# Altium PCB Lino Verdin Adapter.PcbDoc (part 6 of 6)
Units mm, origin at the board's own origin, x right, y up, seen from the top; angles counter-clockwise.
Board outline 69.6 x 35 mm, 8 copper layers (Top Layer, Mid 1, GND 1, Mid 2, Mid 3, GND 2, Mid 4, Bottom Layer), stack 1.198 mm thick; 208 components, 258 nets, 1063 pads, 1090 vias.
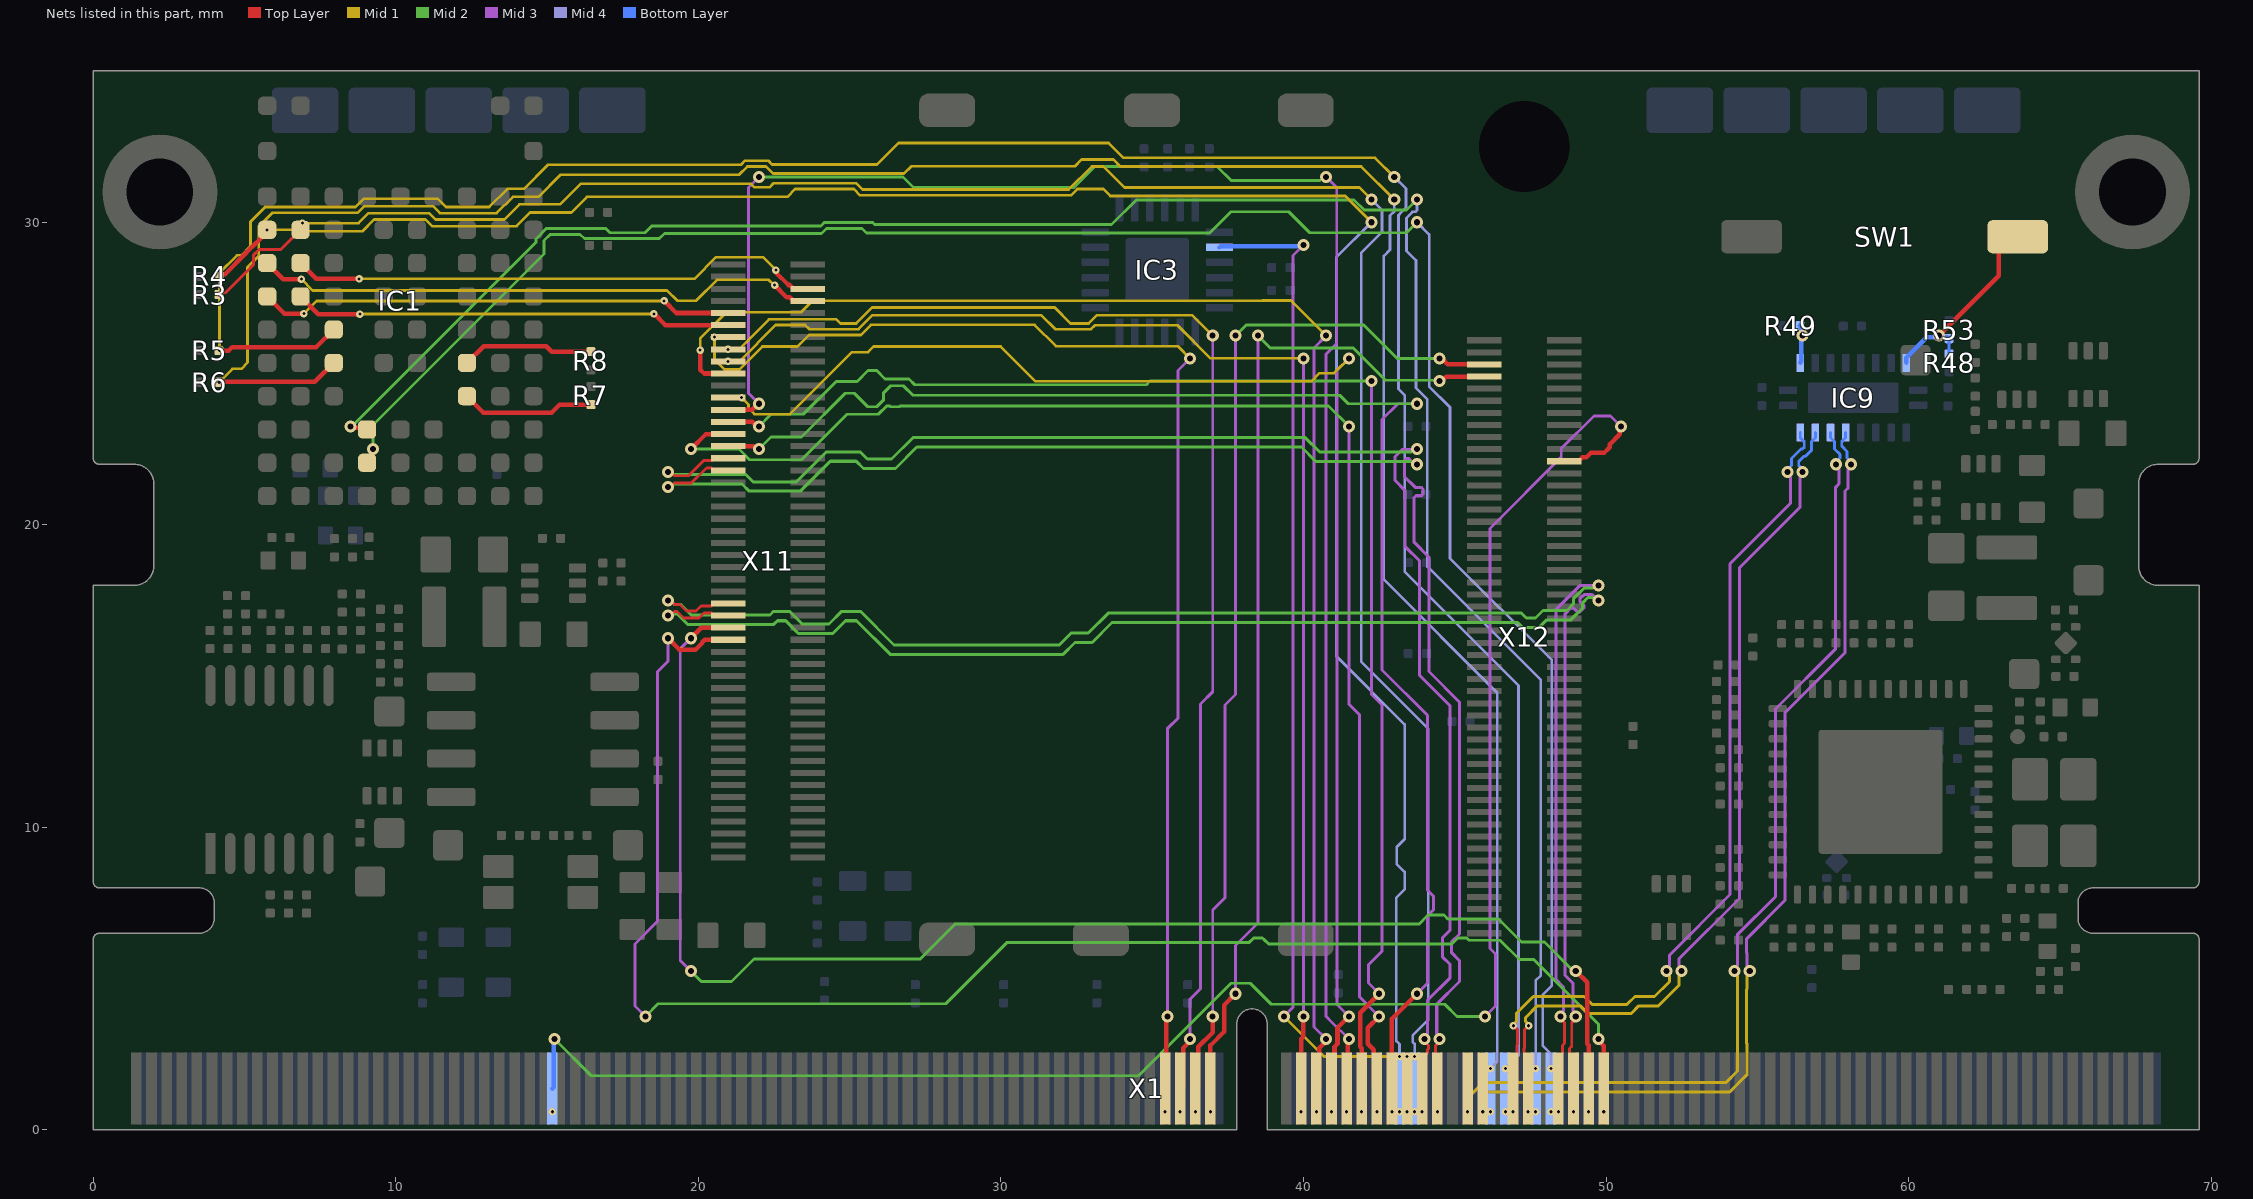
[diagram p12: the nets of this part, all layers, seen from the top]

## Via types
v1: diameter 0.4, hole 0.2, Top Layer to Bottom Layer, tented both sides, 600 vias
v2: diameter 0.25, hole 0.1, Mid 4 to Bottom Layer, tented both sides, 229 vias
v3: diameter 0.25, hole 0.1, Top Layer to Mid 1, tented both sides, 216 vias
v4: diameter 0.25, hole 0.1, Top Layer to Mid 1, tented top, 41 vias
v5: diameter 0.4, hole 0.2, Top Layer to Bottom Layer, 4 vias

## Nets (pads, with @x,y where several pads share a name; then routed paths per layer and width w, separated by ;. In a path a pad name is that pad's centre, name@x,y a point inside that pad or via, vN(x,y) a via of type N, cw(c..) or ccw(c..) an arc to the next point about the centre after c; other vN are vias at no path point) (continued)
SPI_2_MOSI: X1.56 X12.S22 | length 59.7
  Top Layer w0.15: X12.S22@48.62,22.1 48.645,22.125 49.115,22.125 49.215,22.225 49.341,22.225 49.491,22.375 49.935,22.375 50.125,22.565 50.125,22.655 50.459,22.99 50.459,23.209 v1(50.5,23.25)
  Mid 3 w0.095: v1(46,3.75) 46.35,4.1 46.35,5.81 46.16,6 46.16,19.88 48.522,22.242 48.522,22.522 49.598,23.598 50.152,23.598 v1(50.5,23.25)
  Mid 2 w0.095: v1(15.25,3) 16.46,1.79 34.549,1.79 36.106,3.347 37.606,4.848 38.243,4.848 38.938,4.152 44.668,4.152 45.07,3.75 v1(46,3.75)
  Bottom Layer w0.15: X1.56@15.175,1.362 15.213,1.4 15.213,2.963 v1(15.25,3)
  other v2: 15.175,0.6
UART_1_CTS: IC1.H8 X11.P6 | length 17.8
  Top Layer w0.15: IC1.H8@6.85,28.65 7.37,28.13 v3(8.79,28.13) ; v3(22.56,28.42) 22.579,28.401 22.579,28.323 22.978,27.925 23.025,27.925 23.125,27.825 23.595,27.825 X11.P6@23.62,27.8
  Mid 1 w0.09: v3(8.79,28.13) 19.868,28.13 20.583,28.845 22.143,28.845 22.56,28.428 v3(22.56,28.42)
UART_1_RTS: IC1.H9 X11.P8 | length 19
  Top Layer w0.15: IC1.H9@5.75,28.65 6.28,28.12 v3(6.88,28.12) ; v3(22.52,27.92) 22.915,27.525 23.025,27.525 23.125,27.425 23.595,27.425 X11.P8@23.62,27.4
  Mid 1 w0.09: v3(6.88,28.12) 7.253,27.747 18.965,27.747 19.307,27.405 19.925,27.405 20.615,28.095 22.327,28.095 22.502,27.92 v3(22.52,27.92)
UART_1_RXD: IC1.G8 X11.P11 | length 14.5
  Top Layer w0.15: IC1.G8@6.85,27.55 7.44,26.96 v3(8.81,26.96) ; v4(18.53,26.97) 18.543,26.97 18.913,26.6 X11.P11@20.98,26.6
  Mid 1 w0.09: v3(8.81,26.96) 8.815,26.965 18.525,26.965 v4(18.53,26.97)
UART_1_TXD: IC1.G9 X11.P9 | length 15.8
  Top Layer w0.15: IC1.G9@5.75,27.55 6.32,26.98 v3(6.96,26.98) ; v4(18.87,27.4) 19.27,27 X11.P9@20.98,27
  Mid 1 w0.09: v3(6.96,26.98) 7.38,27.4 v4(18.87,27.4)
UART_2_CTS: X1.143 X12.S7 | length 33.7
  Top Layer w0.15: X1.143@36.925,1.362 36.925,2.791 37.375,3.241 37.375,4.125 v1(37.75,4.5) ; v1(44.5,24.75) 44.568,24.75 44.718,24.9 X12.S7@45.98,24.9
  Mid 3 w0.095: v1(37.75,4.5) 37.75,6.09 38.5,6.84 v1(38.5,26.25)
  Mid 2 w0.095: v1(38.5,26.25) 38.902,25.847 41.644,25.847 42.716,24.776 44.474,24.776 v1(44.5,24.75)
  other v3: 36.925,0.6
UART_2_RTS: X1.141 X12.S5 | length 34.3
  Top Layer w0.15: X1.141@36.425,1.362 36.525,1.462 36.525,2.745 37,3.22 v1(37,3.75) ; v1(44.5,25.5) 44.568,25.5 44.768,25.3 X12.S5@45.98,25.3
  Mid 3 w0.095: v1(37,3.75) 37,7.27 37.403,7.673 37.403,13.356 37.403,14.042 37.75,14.39 v1(37.75,26.25)
  Mid 2 w0.095: v1(37.75,26.25) 38.097,26.597 42.003,26.597 43.1,25.5 v1(44.5,25.5)
  other v3: 36.425,0.6
UART_2_RXD: X1.137 X11.P13 | length 42.1
  Top Layer w0.15: X1.137@35.425,1.362 35.463,1.4 35.463,3.712 v1(35.5,3.75)
  Mid 3 w0.095: v1(35.5,3.75) 35.5,13.259 35.848,13.606 35.848,25.097 v1(36.25,25.5)
  Mid 1 w0.09: v4(20.53,26.2) 20.53,25.468 20.868,25.13 21.355,25.13 22.115,25.89 23.27,25.89 23.655,26.275 25.372,26.275 25.707,26.61 31.11,26.61 31.815,25.905 35.845,25.905 v1(36.25,25.5)
  other v3: 35.425,0.6
UART_2_TXD: X1.139 X11.P15 | length 42.6
  Top Layer w0.15: X1.139@35.925,1.362 36.025,1.462 36.025,2.707 36.25,2.932 v1(36.25,3)
  Mid 3 w0.095: v1(36.25,3) 36.25,4.32 36.598,4.668 36.598,14.08 37,14.483 v1(37,26.25)
  Mid 1 w0.09: v4(20.98,25.8) 21.34,25.8 22.33,26.79 24.56,26.79 24.695,26.655 25.214,26.655 25.739,27.18 31.78,27.18 32.305,26.655 32.898,26.655 33.173,26.93 36.32,26.93 v1(37,26.25)
  other v3: 35.925,0.6
UART_3_RXD: X1.147 X11.P17 | length 44.6
  Top Layer w0.15: X1.147@39.925,1.362 39.925,3.005 40,3.08 v1(40,3.75)
  Mid 3 w0.095: v1(40,3.75) v1(40,25.5)
  Mid 1 w0.09: v4(20.98,25.4) 21.356,25.4 22.556,26.6 23.53,26.6 23.665,26.465 25.293,26.465 25.758,26.93 31.33,26.93 31.795,26.465 32.977,26.465 33.107,26.595 35.836,26.595 36.931,25.5 v1(40,25.5)
  other v3: 39.925,0.6
UART_3_TXD: X1.149 X11.P19 | length 49
  Top Layer w0.15: v3(20.06,25.77) 20.06,25.128 20.188,25 X11.P19@20.98,25 ; X1.149@40.425,1.362 40.525,1.462 40.525,2.707 40.75,2.932 v1(40.75,3)
  Mid 3 w0.095: v1(40.75,3) 40.348,3.402 40.348,25.848 v1(40.75,26.25)
  Mid 1 w0.09: v3(20.06,25.77) 20.06,26.16 20.925,27.025 23.395,27.025 23.775,27.405 31.607,27.405 38.643,27.405 38.648,27.41 39.59,27.41 v1(40.75,26.25)
  other v3: 40.425,0.6
UART_4_RXD: X1.151 X11.P23 | length 47.2
  Top Layer w0.15: X11.P23@20.98,24.2 v4(21.43,24.2) ; X1.151@40.925,1.362 41.025,1.462 41.025,2.745 41.125,2.845 41.125,3.155 41.125,3.375 v1(41.5,3.75)
  Mid 3 w0.095: v1(41.5,3.75) 41.11,4.14 41.11,25.11 v1(41.5,25.5)
  Mid 1 w0.09: v4(21.43,24.2) 21.655,23.975 21.655,23.857 21.857,23.655 23.025,23.655 25.075,25.705 25.608,25.705 25.793,25.89 29.99,25.89 31.14,24.74 40.265,24.74 40.535,25.01 41.01,25.01 v1(41.5,25.5)
  other v3: 40.925,0.6
UART_4_TXD: X1.153 X11.P25 | length 59.1
  Top Layer w0.15: X11.P25@20.98,23.8 21.775,23.8 21.975,24 v1(22,24) ; X1.153@41.425,1.362 41.462,1.4 41.462,2.962 v1(41.5,3)
  Mid 3 w0.095: v1(22,24) 21.653,24.348 21.653,31.153 v1(22,31.5) ; v1(40.75,31.5) 41.1,31.15 41.1,25.99 40.75,25.64 40.75,3.75 40.945,3.555 v1(41.5,3)
  Mid 2 w0.095: v1(22,31.5) 26.759,31.5 27.106,31.153 32.411,31.153 33.106,31.848 37.144,31.848 37.611,31.38 40.547,31.38 40.667,31.5 v1(40.75,31.5)
  other v3: 41.425,0.6
USB_1_D_N: X1.163 X11.P33 | length 51.4
  Top Layer w0.095: v1(19,21.75) 19.077,21.75 19.208,21.619 19.669,21.619 20.169,22.119 20.429,22.119 20.51,22.2 X11.P33@20.98,22.2 ; X1.163@43.925,1.362 43.925,2.375 44.102,2.552 44.102,2.649 44.131,2.678 44.131,2.792 44,2.923 v1(44,3)
  Mid 3 w0.1: v1(43.75,22.5) 43.746,22.496 43.272,22.496 43.031,22.256 43.031,21.464 43.35,21.145 43.35,19.29 43.84,18.8 43.84,15.02 44.85,14.01 44.85,6.605 44.59,6.345 44.59,5.727 44.85,5.467 44.85,5.033 44.095,4.278 44.095,3.176 44,3.081 v1(44,3)
  Mid 2 w0.1: v1(19,21.75) 19.081,21.75 19.176,21.655 21.573,21.655 21.806,21.422 23.244,21.422 24.232,22.41 25.345,22.41 25.583,22.172 26.386,22.172 27.094,22.88 40.06,22.88 40.535,22.405 43.574,22.405 43.669,22.5 v1(43.75,22.5)
  other v3: 43.925,0.6
USB_1_D_P: X1.165 X11.P35 | length 51.3
  Top Layer w0.095: v1(19,21.25) 19.077,21.25 19.208,21.381 19.767,21.381 20.267,21.881 20.429,21.881 20.51,21.8 X11.P35@20.98,21.8 ; X1.165@44.425,1.362 44.369,1.418 44.369,2.792 44.5,2.923 v1(44.5,3)
  Mid 3 w0.1: v1(43.75,22) 43.669,22 43.483,22.186 43.4,22.186 43.341,22.127 43.341,21.592 43.693,21.24 43.891,21.24 43.95,21.181 43.95,21.019 43.891,20.96 43.719,20.96 43.66,20.901 43.66,19.418 44.15,18.928 44.15,15.148 45.16,14.138 45.16,6.477 44.9,6.217 44.9,5.855 45.16,5.595 45.16,4.905 44.405,4.15 44.405,3.176 44.5,3.081 v1(44.5,3)
  Mid 2 w0.1: v1(19,21.25) 19.081,21.25 19.176,21.345 21.445,21.345 21.678,21.112 23.372,21.112 24.36,22.1 25.217,22.1 25.455,21.862 26.514,21.862 27.222,22.57 39.932,22.57 40.407,22.095 43.574,22.095 43.669,22 v1(43.75,22)
  other v3: 44.425,0.6
USB_1_EN: X1.155 X11.P27 | length 46.5
  Top Layer w0.15: X11.P27@20.98,23.4 21.782,23.4 21.932,23.25 v1(22,23.25) ; X1.155@41.925,1.362 41.925,2.691 41.875,2.741 41.875,3.875 v1(42.5,4.5)
  Mid 3 w0.095: v1(42.25,24.75) 42.25,14.39 42.593,14.047 42.593,13.649 42.598,13.644 42.598,11.856 42.593,11.851 42.593,5.903 42.148,5.458 42.148,4.852 v1(42.5,4.5)
  Mid 2 w0.095: v1(22,23.25) 22.403,23.653 23.467,23.653 24.554,24.74 25.249,24.74 25.606,25.098 25.894,25.098 26.171,24.82 26.96,24.82 27.15,24.63 34.81,24.63 34.93,24.75 v1(42.25,24.75)
  other v3: 41.925,0.6
USB_1_ID: IC3.2 X1.161 | length 33.2
  Mid 3 w0.095: v1(39.35,3.75) 39.652,4.052 39.652,28.902 v1(40,29.25)
  Mid 1 w0.09: v1(39.35,3.75) 40.675,2.425 v3(43.425,2.425)
  Bottom Layer w0.15: IC3.2@37.22,29.172 37.259,29.211 39.961,29.211 v1(40,29.25)
  other v3: 43.425,0.6
USB_1_OC#: X1.157 X11.P29 | length 47
  Top Layer w0.15: v1(19.75,22.5) 20.25,23 X11.P29@20.98,23 ; X1.157@42.425,1.362 42.325,1.462 42.325,2.645 42.125,2.845 42.125,3.375 v1(42.5,3.75)
  Mid 3 w0.095: v1(41.5,23.255) 41.5,14.07 41.848,13.723 41.848,6.794 41.84,6.787 41.848,6.779 41.848,4.402 v1(42.5,3.75)
  Mid 2 w0.095: v1(19.75,22.5) 21.34,22.5 21.69,22.15 23.409,22.15 24.911,23.653 25.947,23.653 26.224,23.93 26.329,23.93 26.356,23.902 26.644,23.902 26.671,23.93 40.825,23.93 v1(41.5,23.255)
  other v3: 42.425,0.6
USB_1_VBUS: X1.159 X11.P31 | length 49.2
  Top Layer w0.15: X11.P31@20.98,22.6 21.832,22.6 21.932,22.5 v1(22,22.5) ; X1.159@42.925,1.362 42.925,3.675 v1(43.75,4.5)
  Mid 3 w0.095: v1(43.75,4.5) 44.098,4.847 44.098,7.08 44.293,7.275 44.293,7.725 44.098,7.92 44.098,13.702 42.6,15.2 42.6,23.48 43.12,24 v1(43.75,24)
  Mid 2 w0.095: v1(22,22.5) 22.403,22.903 23.411,22.903 24.856,24.348 25.153,24.348 25.597,23.903 25.894,23.903 26.125,24.134 26.125,24.366 26.356,24.597 26.773,24.597 27.09,24.28 41.2,24.28 41.48,24 v1(43.75,24)
  other v3: 42.925,0.6
USB_2_D_N: X1.181 X11.P57 | length 52.9
  Top Layer w0.095: v1(19,17.5) 19.077,17.5 19.208,17.369 19.39,17.369 19.606,17.153 19.92,17.153 20.086,17.319 20.429,17.319 20.51,17.4 X11.P57@20.98,17.4 ; X1.181@48.425,1.362 48.553,1.49 48.553,2.555 48.556,2.558 48.556,2.791 48.631,2.866 48.631,3.542 48.5,3.673 v1(48.5,3.75)
  Mid 3 w0.1: v1(48.5,3.75) 48.5,3.831 48.595,3.926 48.595,4.722 48.34,4.977 48.34,17.19 49.15,18 v1(49.75,18)
  Mid 2 w0.1: v1(19,17.5) 19.081,17.5 19.215,17.366 19.42,17.366 19.766,17.02 22.368,17.02 22.486,17.138 23.014,17.138 23.432,16.72 24.318,16.72 24.736,17.138 25.358,17.138 26.466,16.03 31.93,16.03 32.322,16.422 32.886,16.422 33.544,17.08 47.206,17.08 47.364,16.922 47.667,16.922 47.915,17.17 48.708,17.17 48.918,17.38 48.918,17.551 49.272,17.905 49.574,17.905 49.669,18 v1(49.75,18)
  other v3: 48.425,0.6
USB_2_D_P: X1.183 X11.P59 | length 52.9
  Top Layer w0.095: v1(19,17) 19.077,17 19.208,17.131 19.291,17.131 19.507,16.915 20.018,16.915 20.185,17.081 20.429,17.081 20.51,17 X11.P59@20.98,17 ; X1.183@48.925,1.362 48.797,1.49 48.797,2.555 48.794,2.558 48.794,2.693 48.869,2.768 48.869,3.542 49,3.673 v1(49,3.75)
  Mid 3 w0.1: v1(49,3.75) 49,3.831 48.905,3.926 48.905,4.85 48.65,5.105 48.65,17.062 48.838,17.249 48.921,17.249 49.049,17.121 49.131,17.121 49.264,17.254 49.264,17.336 49.136,17.464 49.136,17.547 49.278,17.69 49.541,17.69 49.731,17.5 v1(49.75,17.5)
  Mid 2 w0.1: v1(19,17) 19.056,17.056 19.291,17.056 19.638,16.71 22.496,16.71 22.614,16.828 22.886,16.828 23.304,16.41 24.446,16.41 24.864,16.828 25.229,16.828 26.337,15.72 32.058,15.72 32.45,16.112 33.014,16.112 33.672,16.77 47.078,16.77 47.236,16.612 47.795,16.612 48.043,16.86 48.836,16.86 49.228,17.251 49.228,17.423 49.4,17.595 49.574,17.595 49.669,17.5 v1(49.75,17.5)
  other v3: 48.925,0.6
USB_2_EN: X1.185 X11.P61 | length 47.8
  Top Layer w0.15: v1(19.75,16.25) 20.1,16.6 X11.P61@20.98,16.6 ; v1(49,5.25) 49.375,4.875 49.375,3.373 49.375,2.84 49.425,2.79 X1.185@49.425,1.362
  Mid 3 w0.095: v1(19.75,5.25) 19.403,5.598 19.403,15.903 v1(19.75,16.25)
  Mid 2 w0.095: v1(19.75,5.25) 20.098,4.902 21.093,4.902 21.842,5.652 27.332,5.652 28.48,6.8 43.817,6.8 44.115,7.097 44.644,7.097 44.771,6.97 46.444,6.97 47.207,6.207 47.962,6.207 48.919,5.25 v1(49,5.25)
  other v3: 49.425,0.6
USB_2_OC#: X1.187 X11.P63 | length 51.5
  Top Layer w0.15: v1(19,16.25) 19.375,15.875 19.905,15.875 20.125,16.095 20.125,16.112 20.213,16.2 X11.P63@20.98,16.2 ; v1(49.75,3) 49.75,2.95 49.925,2.775 X1.187@49.925,1.362
  Mid 3 w0.095: v1(18.25,3.75) 17.903,4.097 17.903,6.144 18.653,6.894 18.653,15.144 19,15.491 v1(19,16.25)
  Mid 2 w0.095: v1(18.25,3.75) 18.67,4.17 28.179,4.17 30.209,6.2 38.209,6.2 38.294,6.285 38.356,6.347 38.644,6.347 38.706,6.285 38.851,6.14 44.899,6.14 45.106,6.348 45.394,6.348 45.471,6.27 46.497,6.27 47.137,5.63 47.611,5.63 49.75,3.491 v1(49.75,3)
  other v3: 49.925,0.6
USB_2_SSRX_N: IC9.19 X1.175 | length 28.6
  Top Layer w0.095: X1.175@46.925,1.362 47.052,1.49 47.052,2.555 47.056,2.558 47.056,2.791 47.071,2.806 47.071,3.309 46.94,3.44 v3(46.94,3.443)
  Mid 3 w0.1: v1(52,5.25) 52,5.331 52.095,5.426 52.095,5.775 54.1,7.78 54.1,18.708 56.1,20.708 56.1,21.267 56.095,21.272 56.095,21.574 56,21.669 v1(56,21.75)
  Mid 1 w0.1: v3(46.94,3.443) 46.94,3.481 47.035,3.576 47.035,3.846 47.599,4.41 49.273,4.41 49.533,4.15 50.695,4.15 50.955,4.41 51.605,4.41 52.095,4.9 52.095,5.074 52,5.169 v1(52,5.25)
  Bottom Layer w0.095: v1(56,21.75) 56,21.827 56.131,21.958 56.131,22.191 56.443,22.503 56.492,22.503 56.551,22.562 56.551,22.744 56.42,22.875 IC9.19@56.42,23.05
  other v3: 46.925,0.6
USB_2_SSRX_P: IC9.18 X1.177 | length 28.6
  Top Layer w0.095: X1.177@47.425,1.362 47.297,1.49 47.297,2.555 47.294,2.558 47.294,2.693 47.309,2.708 47.309,3.309 47.44,3.44 v3(47.44,3.443)
  Mid 3 w0.1: v1(52.5,5.25) 52.5,5.331 52.405,5.426 52.405,5.647 54.41,7.652 54.41,18.58 56.41,20.58 56.41,21.395 56.405,21.4 56.405,21.574 56.5,21.669 v1(56.5,21.75)
  Mid 1 w0.1: v3(47.44,3.443) 47.44,3.481 47.345,3.576 47.345,3.718 47.728,4.1 49.145,4.1 49.405,3.84 50.823,3.84 51.083,4.1 51.733,4.1 52.405,4.772 52.405,5.074 52.5,5.169 v1(52.5,5.25)
  Bottom Layer w0.095: v1(56.5,21.75) 56.5,21.827 56.369,21.958 56.369,22.093 56.541,22.265 56.59,22.265 56.789,22.463 56.789,22.744 56.92,22.875 IC9.18@56.92,23.05
  other v3: 47.425,0.6
USB_2_SSTX_N: IC9.17 X1.169 | length 32.5
  Mid 3 w0.1: v1(54.25,5.25) 54.25,5.331 54.345,5.426 54.345,5.722 54.34,5.727 54.34,6.45 55.6,7.71 55.6,13.908 57.59,15.898 57.59,21.242 57.695,21.347 57.695,21.824 57.6,21.919 v1(57.6,22)
  Mid 1 w0.1: v3(45.425,0.6) 45.425,0.639 45.52,0.734 45.52,1.141 45.939,1.56 53.958,1.56 54.345,1.947 54.345,2.722 54.34,2.727 54.34,4.773 54.345,4.778 54.345,5.074 54.25,5.169 v1(54.25,5.25)
  Bottom Layer w0.095: IC9.17@57.42,23.05 57.42,22.875 57.551,22.744 57.551,22.509 57.731,22.329 57.731,22.208 57.6,22.077 v1(57.6,22)
USB_2_SSTX_P: IC9.16 X1.171 | length 32.5
  Mid 3 w0.1: v1(54.75,5.25) 54.75,5.331 54.655,5.426 54.655,5.85 54.65,5.855 54.65,6.322 55.91,7.582 55.91,13.78 57.9,15.77 57.9,21.114 58.005,21.219 58.005,21.824 58.1,21.919 v1(58.1,22)
  Mid 1 w0.1: v3(45.925,0.6) 45.925,0.639 45.83,0.734 45.83,1.013 46.067,1.25 54.087,1.25 54.655,1.818 54.655,2.85 54.65,2.855 54.65,4.645 54.655,4.65 54.655,5.074 54.75,5.169 v1(54.75,5.25)
  Bottom Layer w0.095: IC9.16@57.92,23.05 57.92,22.875 57.789,22.744 57.789,22.607 57.969,22.427 57.969,22.208 58.1,22.077 v1(58.1,22)
USBMUX#: IC9.9 R48.1 R53.2 SW1.1 | length 7
  Top Layer w0.15: v1(61,26.25) 62.98,28.23 62.98,29.182 63.318,29.52 SW1.1@63.61,29.52
  Bottom Layer w0.1: R48.1@61.34,25.65 R53.2@61.34,26.15
  Bottom Layer w0.15: IC9.9@59.92,25.35 59.92,25.525 60.597,26.202 60.952,26.202 v1(61,26.25) 61.048,26.202 61.288,26.202 R53.2@61.34,26.15
USBMUX_OE#: IC9.2 R49.2 | length 1.3
  Bottom Layer w0.15: R49.2@56.41,26.58 56.455,26.535 56.455,26.295 v1(56.5,26.25) 56.46,26.21 56.46,25.39 IC9.2@56.42,25.35
WiFi_BT_WKUP_DEV: IC1.J9 R4.2 X1.160 | length 69.6
  Top Layer w0.15: R4.2@4.15,28.21 4.225,28.285 4.355,28.285 5.075,29.005 5.075,29.017 5.383,29.325 5.395,29.325 5.571,29.501 5.571,29.571 v4(5.75,29.75)
  Mid 4 w0.09: v1(42.25,30) 41.08,28.83 41.08,26.408 41.095,26.393 41.095,15.655 43.345,13.405 43.345,9.607 43.08,9.342 43.08,8.787 43.345,8.522 43.345,7.952 43.07,7.677 43.07,2.94 43.175,2.835 v2(43.175,2.425)
  Mid 1 w0.09: v4(5.75,29.75) 6.748,29.75 6.798,29.7 7.022,29.7 8.89,29.7 9.28,30.09 10.98,30.09 11.2,29.87 13.99,29.87 14.44,30.32 15.8,30.32 16.32,30.84 22.94,30.84 23.195,31.095 25.143,31.095 25.158,31.08 25.348,30.89 32.319,30.89 32.509,31.08 32.524,31.095 33.393,31.095 33.618,30.87 41.38,30.87 v1(42.25,30)
  other v2: 43.175,0.6
WiFi_BT_WKUP_HOST: IC1.E7 R6.2 X1.172 | length 79.8
  Top Layer w0.15: v4(4.15,24.71) 4.165,24.725 7.325,24.725 IC1.E7@7.95,25.35
  Mid 4 w0.09: v1(43,30.75) 43,30.36 42.86,30.22 42.86,29.09 42.655,28.885 42.655,18.195 46.405,14.445 46.405,2.255 v2(46.175,2.025)
  Mid 1 w0.09: v4(4.15,24.71) 4.595,25.155 4.893,25.155 5.1,25.362 5.1,28.52 5.47,28.89 5.47,29.852 5.933,30.315 8.746,30.315 8.961,30.53 11.23,30.53 11.46,30.3 13.33,30.3 13.87,30.84 14.71,30.84 15.44,31.57 21.345,31.57 21.62,31.845 22.231,31.845 22.466,31.61 26.8,31.61 27.04,31.85 32.45,31.85 32.67,32.07 33.72,32.07 33.945,31.845 41.905,31.845 v1(43,30.75)
  other v2: 46.175,0.6
WiFi_CONFIG0: IC1.D3 R7.2 | length 4.4
  Top Layer w0.15: IC1.D3@12.35,24.25 12.89,23.71 15.15,23.71 15.41,23.97 R7.2@16.45,23.97
WiFi_CONFIG1: IC1.E3 R8.2 | length 4.4
  Top Layer w0.15: IC1.E3@12.35,25.35 12.905,25.905 14.975,25.905 15.159,25.721 R8.2@16.45,25.721
WiFi_LTE_COEX_IN: IC1.C6 X1.178 | length 70.3
  Top Layer w0.15: v1(8.5,23.25) 8.548,23.202 8.998,23.202 IC1.C6@9.05,23.15
  Mid 2 w0.095: v1(8.5,23.25) 8.541,23.25 14.63,29.339 14.63,29.45 14.973,29.793 16.937,29.793 17.078,29.652 18.232,29.652 18.46,29.88 24.05,29.88 24.158,29.988 25.763,29.988 25.82,29.93 33.66,29.93 34.47,30.74 41.67,30.74 42.008,30.403 43.402,30.403 v1(43.75,30.75)
  Mid 4 w0.09: v1(43.75,30.75) 43.75,30.398 43.697,30.345 43.607,30.345 43.405,30.143 43.405,29.055 43.72,28.74 43.72,24.518 44.095,24.143 44.095,18.615 47.845,14.865 47.845,5.107 47.675,4.937 v2(47.675,2.025)
  other v2: 47.675,0.6
WiFi_LTE_COEX_OUT: IC1.B6 X1.180 | length 69.7
  Top Layer w0.15: IC1.B6@9.05,22.05 9.202,22.202 9.202,22.452 v1(9.25,22.5)
  Mid 2 w0.095: v1(9.25,22.5) 9.25,23.3 14.902,28.952 14.902,29.394 15.106,29.598 16.092,29.598 16.233,29.457 18.707,29.457 18.878,29.628 24.073,29.628 24.238,29.793 25.407,29.793 25.557,29.643 36.901,29.643 37.606,30.348 39.512,30.348 40.207,29.653 43.402,29.653 v1(43.75,30)
  Mid 4 w0.09: v1(43.75,30) 44.155,29.595 44.155,24.575 44.845,23.885 44.845,18.893 48.21,15.528 48.21,4.77 47.905,4.465 47.905,2.785 48.175,2.515 v2(48.175,2.025)
  other v2: 48.175,0.6
WiFi_W_WKUP_DEV: IC1.J8 R3.2 X1.162 | length 70.9
  Top Layer w0.1: R3.2@4.15,27.61 4.212,27.672 4.372,27.672 5.3,28.6 5.3,28.924 5.476,29.1 6.2,29.1 IC1.J8@6.85,29.75
  Top Layer w0.15: IC1.J8@6.85,29.75 6.85,29.91 v4(6.91,29.97)
  Mid 4 w0.09: v1(42.25,30.75) 42.595,30.405 42.595,29.675 41.905,28.985 41.905,15.475 44.12,13.26 44.12,3.632 43.61,3.122 43.61,2.902 43.675,2.837 v2(43.675,2.425)
  Mid 1 w0.09: v4(6.91,29.97) 8.77,29.97 9.1,30.3 11.1,30.3 11.31,30.09 13.59,30.09 14.09,30.59 15.43,30.59 16.11,31.27 21.742,31.27 21.857,31.155 22.345,31.155 22.475,31.285 25.222,31.285 25.427,31.08 32.24,31.08 33.005,31.845 33.393,31.845 34.088,31.15 41.85,31.15 v1(42.25,30.75)
  other v2: 43.675,0.6
WiFi_W_WKUP_HOST: IC1.F7 R5.2 X1.174 | length 80.1
  Top Layer w0.15: v4(4.17,25.76) 4.48,25.76 4.595,25.875 7.375,25.875 IC1.F7@7.95,26.45
  Mid 4 w0.09: v1(43,31.5) 43.39,31.11 43.39,30.481 43.176,30.268 43.141,30.233 43.141,24.489 43.345,24.285 43.345,18.455 47.11,14.69 47.11,2.46 v2(46.675,2.025)
  Mid 1 w0.09: v4(4.17,25.76) 4.17,28.33 4.745,28.905 4.893,28.905 5.195,29.207 5.195,30.015 5.685,30.505 8.667,30.505 8.942,30.78 11.382,30.78 11.657,30.505 13.085,30.505 13.685,31.105 14.235,31.105 15.03,31.9 21.406,31.9 21.541,32.035 22.309,32.035 22.439,31.905 25.905,31.905 26.62,32.62 33.56,32.62 34.05,32.13 42.37,32.13 v1(43,31.5)
  other v2: 46.675,0.6
pads on no net: IC1.B1 IC1.B9 IC1.C1 IC1.C2 IC1.C4 IC1.C5 IC1.C8 IC1.C9 IC1.D1 IC1.D2 IC1.D7 IC1.D9 IC1.E1 IC1.E2 IC1.F1 IC1.F2 IC1.F3 IC1.G1 IC1.G2 IC1.G3 IC1.G4 IC1.G5 IC1.G7 IC1.H1 IC1.H2 IC1.H3 IC1.J1 IC1.J2 IC1.J4 IC1.J5 IC1.K1 IC1.K5 IC1.K9 IC1.L9 IC2.11 IC3. IC3.6 IC3.7 IC3.8 IC5.6 IC6.6 IC17.20 IC17.21 IC17.22 IC17.23 MECH1. MECH1.1 TP3.1 TP4.1 X1.59 X1.61 X1.63 X1.67 X1.69 X1.73 X1.75 X1.79 X1.81 X1.85 X1.87 X1.99 X1.101 X1.105 X1.107 X1.129 X1.131 X1.133 X1.135 X1.164 X1.166 X1.168 X1.176 X1.189 X1.249
copper on no net:
  other v2: 44.175,0.6 44.675,0.6 45.175,0.6 47.175,0.6
  other v3: 15.925,0.6 16.425,0.6 16.925,0.6 17.925,0.6 18.425,0.6 19.425,0.6 19.925,0.6 20.925,0.6 21.425,0.6 22.425,0.6 22.925,0.6 25.925,0.6 26.425,0.6 27.425,0.6 27.925,0.6 33.425,0.6 33.925,0.6 34.425,0.6 34.925,0.6 50.425,0.6 65.425,0.6

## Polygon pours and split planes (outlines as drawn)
GND on Top Layer "GND_L01_P390" (solid, pour order 390): 21.45,11.2 21.65,11 21.65,9.39 21.45,9.19 21.45,8.94 21.58,8.81 22.16,8.81 22.41,9.06 22.41,11.37 22.17,11.61 21.45,11.61
+V1.8 on Top Layer "+V1.8_L01_P358" (solid, pour order 358): 45.75,28.37 45.29,28.83 41.73,28.83 38.3,32.26 34.76,32.26 34.32,31.82 34.32,30.99 34.81,30.5 37.4,30.5 37.99,29.91 37.99,29.21 40.17,27.03 45.13,27.03 45.58,26.58 50.58,26.58 51.4,25.76 51.42,19.73 53.75,17.4 59.02,17.39 59.42,16.99 60.96,16.99 61.26,17.29 61.26,18.41 61.15,18.52 60.84,18.52 60.01,19.35 60.01,19.44 60.01,23.41 61.22,24.62 61.22,25.54 59.88,26.88 56.7,26.88 55.21,28.37
GND on Top Layer "GND_L01_P391" (solid, pour order 391): 21.46,17.6 23.158,17.6 23.155,21.59 21.46,21.59
+V_LINO on Top Layer "+V_LINO_L01_P362" (solid, pour order 362): 22.21,8.7 22.52,9.01 22.52,10.65 23.02,11.15 24.17,11.15 24.33,10.99 24.33,8.46 24.06,8.19 24.13,8.12 24.13,7.85 22.09,5.81 21.24,5.81 20.96,6.09 20.96,6.825 20.615,7.17 15.748,7.178 15.54,7.385 15.54,7.98 15.78,8.22 16.86,8.22 17.34,8.7
GND on Top Layer "GND_L01_P364" (solid, pour order 364): 18.63,7.07 20.61,7.07 20.81,6.87 20.81,6.04 20.57,5.8 17.64,5.8 17.27,6.17 17.27,6.84 17.5,7.07
+V1.8 on Top Layer "+V1.8_L01_P373" (solid, pour order 373): 24.57,6.58 24.57,7.56 24.39,7.74 24.17,7.74 22.13,5.7 17.59,5.7 17.16,6.13 12.18,6.13 11.15,7.16 10.52,7.16 10.32,6.96 10.32,6.38 11.7,5 16.68,5 17.35,4.33 22.32,4.33
+V1.8 on Top Layer "+V1.8_L01_P387" (solid, pour order 387): 5.78,7.08 6.06,7.08 6.28,6.86 6.37,6.86 6.59,7.08 7.1,7.08 7.1,7.22 5.78,7.22
GND on Top Layer "GND_L01_P372" (solid, pour order 372): 5.44,21.35 5.25,21.16 5.25,18.65 5.37,18.53 5.98,18.53 6.05,18.6 6.05,18.67 6.05,21.35
+V1.8 on Top Layer "+V1.8_L01_P371" (solid, pour order 371): 7.33,19.76 7.56,19.53 7.56,18.76 7.28,18.48 6.36,18.48 6.16,18.68 6.16,20.99 6.54,21.37 7.11,21.37 7.33,21.15
+V1.8 on Top Layer "+V1.8_L01_P370" (solid, pour order 370): 9.66,19.6 9.47,19.41 8.94,19.41 8.79,19.56 8.79,20.37 8.5,20.66 8.5,21.24 8.63,21.37 9.46,21.37 9.66,21.17
+V3.3 on Top Layer "+V3.3_L01_P369" (solid, pour order 369): 7.44,19.8 7.72,19.52 7.72,18.85 7.84,18.73 8.14,18.73 8.23,18.82 8.23,20.54 8.39,20.7 8.39,22.56 8.19,22.76 7.66,22.76 7.44,22.54
+V_SODIMM on Top Layer "+V_SODIMM_L01_P368" (solid, pour order 368): 13.96,15.68 14.1,15.54 14.74,15.54 14.88,15.68 14.88,17.62 14.78,17.72 14.18,17.72 14.14,17.68 14.14,17.05 13.96,16.87 13.96,16.78
GND on Top Layer "GND_L01_P367" (solid, pour order 367): 14.91,19.72 14.96,19.72 15.02,19.66 15.02,19.39 14.76,19.13 14.76,18.49 14.69,18.42 12.74,18.42 12.64,18.52 12.64,19.58 12.78,19.72
NetIC5_2 on Top Layer "NETIC5_2_L01_P366" (solid, pour order 366): 14.74,17.93 14.65,17.84 14.14,17.84 14.03,17.73 14.03,17.1 13.85,16.92 13.85,16.09 13.68,15.92 12.91,15.92 12.79,16.04 12.79,18.11 13,18.32 14.62,18.32 14.74,18.2
+V3.3 on Top Layer "+V3.3_L01_P365" (solid, pour order 365): 10.5,16.43 10.99,15.94 11.88,15.94 12.46,16.52 12.46,19.21 11.91,19.76 10.85,19.76 10.5,19.41
+V_SODIMM on Top Layer "+V_SODIMM_L01_P363" (solid, pour order 363): 14.15,8.6 13.77,8.22 12.92,8.22 12.68,7.98 12.68,7.12 12.8,7 14.4,7 14.65,7 14.95,7.3 14.95,8.36 14.71,8.6
GND on Top Layer "GND_L01_P360" (solid, pour order 360): 21.46,22.98 23.154,22.98 23.15,28.15 21.46,28.15
GND on Top Layer "GND_L01_P359" (solid, pour order 359): 46.346,26.16 48.176,26.16 48.176,6.5 46.346,6.5
NetIC6_2 on Top Layer "NETIC6_2_L01_P357" (solid, pour order 357): 62.84,19.93 62.62,20.15 62.62,20.68 62.57,20.73 62.26,20.73 62.22,20.69 62.22,18.91 62.35,18.78 64.18,18.78 64.27,18.87 64.27,19.71 64.05,19.93
+V_SODIMM on Top Layer "+V_SODIMM_L01_P356" (solid, pour order 356): 65.32,21.2 66.36,21.2 66.45,21.11 66.45,20.21 66.28,20.04 62.88,20.04 62.73,20.19 62.73,20.71 63.22,21.2 63.81,21.2
GND on Top Layer "GND_L01_P355" (solid, pour order 355): 65.17,15.05 65.43,14.79 65.43,13.72 65.25,13.54 64.64,13.54 64.49,13.69 63.54,13.69 63.46,13.61 63.46,13.4 63.58,13.28 64.51,13.28 64.85,12.94 66.22,12.94 66.49,13.21 66.49,16.14 66.43,16.2 65.49,16.2 65.24,16.45 65.14,16.45 64.83,16.14 64.83,16.04 65.17,15.7
+V1.8 on Top Layer "+V1.8_L01_P239" (solid, pour order 239): 60.3,16.91 60.115,17.095 60.115,17.725 60.91,18.52 62.26,18.52 62.54,18.24 64.19,18.24 65.17,17.26 65.17,16.62 64.82,16.27 64.73,16.27 64.6,16.4 64.01,16.4 63.63,16.02 61.62,16.02 60.895,15.295 60.115,15.295 59.89,15.07 59.89,14.25 62.01,14.25 62.15,14.11 62.15,12.13 62.45,11.83 62.74,11.83 62.86,11.71 62.86,11.41 62.69,11.24 62.24,11.24 62,11 61.71,11 61.56,11.15 61.56,11.65 61.6,11.69 61.6,13.49 61.382,13.708 56.762,13.712 56.55,13.5 56.55,12.03 56.18,11.66 54.3,11.66 54.18,11.78 54.18,12.56 54.3,12.68 54.5,12.68 54.52,12.7 54.99,12.23 55.75,12.23 55.98,12.46 55.98,14.01 56.22,14.25 58.78,14.25 59.04,14.51 59.04,16.42 60.18,16.42 60.3,16.54
GND on Top Layer "GND_L01_P244" (solid, pour order 244): 63.74,4.94 64.23,4.45 64.52,4.45 64.64,4.57 64.64,5.39 65.05,5.8 65.62,5.8 65.75,5.93 65.75,6.37 65.37,6.75 65.37,8.07 65.28,8.16 64.98,8.16 64.52,7.7 64.52,7.43 64.66,7.29 64.85,7.29 65,7.14 65,6.66 64.88,6.54 63.12,6.54 62.9,6.32 58.6,6.32 58.45,6.17 57.8,6.17 57.65,6.32 54.92,6.32 54.78,6.18 54.78,5.88 54.87,5.79 56.4,5.79 57.25,4.94
+V1.0_ETH on Top Layer "+V1.0_ETH_L01_P246" (solid, pour order 246): 58.77,6.43 59.52,6.43 59.6,6.51 59.6,7.1 59.13,7.57 59.13,7.99 58.5,7.99 58.5,6.7
+V2.5_ETH on Top Layer "+V2.5_ETH_L01_P242" (solid, pour order 242): 61.13,6.43 61.21,6.51 61.21,7.23 60.67,7.77 60.67,7.99 59.97,7.99 59.97,6.49 60.03,6.43
+V2.5_ETH on Top Layer "+V2.5_ETH_L01_P243" (solid, pour order 243): 58.36,6.28 58.41,6.33 58.41,6.8 58.29,6.92 58.13,6.92 57.64,7.41 57.64,7.99 56.98,7.99 56.98,7.65 56.56,7.23 56.56,6.54 56.67,6.43 57.69,6.43 57.84,6.28
+V1.8 on Top Layer "+V1.8_L01_P241" (solid, pour order 241): 62.51,8.65 62.68,8.65 63.15,8.18 63.15,7.83 63.26,7.72 64.08,7.72 64.62,7.18 64.82,7.18 64.89,7.11 64.89,6.68 64.86,6.65 62.86,6.65 62.44,7.07 62.44,7.7 62.04,8.1 56.52,8.1 56.25,7.83 56.25,7.37 56.34,7.28 56.34,6.5 56.29,6.45 55.46,6.45 55.3,6.61 55.3,8.65
+V1.0_ETH on Top Layer "+V1.0_ETH_L01_P256" (solid, pour order 256): 62.24,14.48 63.95,16.19 64.06,16.3 64.57,16.3 64.73,16.14 64.73,16 65.06,15.67 65.06,15 65.32,14.74 65.32,13.72 65.25,13.65 64.6,13.65 64.45,13.8 63.55,13.8 63.4,13.65 62.24,13.65
+V1.0_ETH on Top Layer "+V1.0_ETH_L01_P240" (solid, pour order 240): 56.03,11.15 56.2,10.98 56.52,10.98 56.7,11.16 56.7,11.33 56.48,11.55 54.22,11.55 54.22,10.62 54.94,10.62 55.47,11.15
+V_SODIMM on Top Layer "+V_SODIMM_L01_P245" (solid, remove dead copper, pour order 245): 66.6,3.87 66.5,3.97 66.5,6.13 66.43,6.2 65.98,6.2 65.85,6.07 65.85,5.87 65.68,5.7 65.14,5.7 64.74,5.3 64.74,4.19 65.81,3.12 65.81,0.18 68.07,0.18 68.07,3.23 68.07,3.77 67.97,3.87
GND on Top Layer "GND_L01_P238" (solid, pour order 238): 56.879,8.751 56.663,8.967 56.657,13.367 56.89,13.6 61.25,13.6 61.49,13.36 61.49,9.03 61.22,8.76
+V_SODIMM on Mid 1 "+V_SODIMM_L02_P374" (solid, pour order 374): 67.19,19.99 62.9,24.28 61.68,24.28 61.24,23.84 61.24,21.71 63.35,19.6 63.35,6.86 63.93,6.28 63.93,5.99 65.13,4.79 65.13,3.69 65.65,3.17 65.65,0.48 65.83,0.3 66.31,0.3 68.22,0.3 68.35,0.43 68.35,4.29 66.44,6.2 66.07,6.2 65.65,6.62 65.65,7.8 67.19,9.34
+V3.3 on Bottom Layer "+V3.3_L08_P383" (solid, pour order 383): 48.82,10.43 49.21,10.82 50.14,10.82 50.53,10.43 56.25,10.43 56.98,9.7 57.47,9.7 57.6,9.83 57.6,10.01 57.77,10.18 58.09,10.18 58.24,10.03 58.24,9.19 58.11,9.06 56.71,9.06 55.83,8.18 41.98,8.18 38.91,11.25 30.66,11.25 30.45,11.46 22.84,11.46 21.9,10.52 18.27,10.52 17.33,11.46 17.33,15.32 15.02,17.63 14.29,17.63 14.04,17.38 10.67,17.38 10.24,17.81 10.24,18.51 10.55,18.82 17.29,18.82 22.72,13.39 25.41,13.39 25.94,12.86 40.56,12.86 42.99,10.43
GND on Bottom Layer "GND_L08_P388" (solid, pour order 388): 57.07,7.61 56.87,7.81 56.87,8.41 56.64,8.64 56.64,8.95 56.81,9.12 56.82,9.11 56.9,9.11 57.06,8.95 57.31,8.95 57.59,9.23 57.66,9.23 57.99,8.9 57.99,8.82 57.45,8.28 57.45,7.67 57.39,7.61
GND on Bottom Layer "GND_L08_P386" (solid, pour order 386): 36.61,27.17 36.42,26.98 33.89,26.98 33.7,27.17 33.7,29.69 33.87,29.86 36.37,29.86 36.61,29.62
+V1.8 on Bottom Layer "+V1.8_L08_P384" (solid, pour order 384): 57.09,20.89 57.65,20.33 57.65,18.84 57.87,18.62 60.24,18.62 61.92,20.3 61.92,24.04 61.76,24.2 60.06,24.2 59.89,24.37 59.89,24.7 60.51,25.32 61.84,25.32 63.14,24.02 63.14,19.83 62.35,19.04 62.35,11.33 62.6,11.08 62.6,10.21 62.35,9.96 62.35,8.21 62.63,7.93 63.32,7.93 63.56,7.69 63.56,7.29 63.31,7.04 62.24,7.04 60.8,8.48 60.8,10.98 61.23,11.41 61.23,14.16 59.56,15.83 34.86,15.83 29.8,20.89 29.8,21.12 26.11,24.81 21.96,24.81 17.5,20.35 11.46,20.35 9.92,18.81 9.92,17.37 13.71,13.58 13.71,7.85 14.41,7.15 22.62,7.15 24.16,8.69 26.85,8.69 27.19,8.35 27.19,7.56 26.98,7.35 24.84,7.35 24.56,7.07 23.97,7.07 22.37,5.47 11.39,5.47 10.7,6.16 5.76,6.16 4.1,7.82 4.1,13.91 3.1,14.91 3.1,22.71 2.56,23.25 2.56,27.69 4.78,29.91 29.38,29.91 33.97,25.32 39.31,25.32 43.74,20.89
+V2.5_ETH on Bottom Layer "+V2.5_ETH_L08_P382" (solid, pour order 382): 56.91,7.13 57.18,6.86 57.46,6.86 57.64,7.04 57.96,7.04 58.3,7.38 58.3,8.55 58.19,8.66 57.98,8.66 57.55,8.23 57.55,7.66 57.38,7.49 57.13,7.49 56.91,7.27
+V_SODIMM on Bottom Layer "+V_SODIMM_L08_P381" (solid, pour order 381): 55.74,8.07 57.06,6.75 57.5,6.75 57.68,6.93 65.09,6.93 65.82,6.2 66.34,6.2 66.5,6.04 66.5,4.04 66.64,3.9 67.23,3.9 67.39,3.74 67.39,3.35 67.21,3.17 64.86,3.17 64.14,3.89 63.36,3.89 62.72,4.53 42.45,4.53 41.57,5.41 40.48,5.41 38.3,7.59 34.31,7.59 33.72,7 28.36,7 27.97,7.39 27.97,7.71 26.88,8.8 25.91,8.8 24.12,8.8 22.58,7.26 14.46,7.26 13.81,7.91 13.81,17 14.33,17.52 14.98,17.52 17.22,15.28 17.22,11.42 18.23,10.41 21.95,10.41 22.89,11.35 28.46,11.35 29.34,10.47 29.72,10.47 30.4,11.15 38.86,11.15 41.94,8.07
+V1.8 on Mid 2 "+V1.8_L04_P376" (solid, pour order 376): 40.63,9.05 40.85,8.83 42.12,8.83 42.51,8.44 48.2,8.44 48.68,8.92 52.35,8.92 53.03,9.6 54.39,9.6 56.86,7.13 56.86,6.69 57.23,6.32 61,6.32 61.42,6.74 61.42,7.78 61.41,7.79 61.79,8.17 63.18,8.17 63.48,7.87 63.48,6.6 63.17,6.29 63.17,4.66 62.35,3.84 56.88,3.84 56.49,3.84 54.9,5.43 54.05,5.43 53.29,6.19 50.55,6.19 49.85,6.89 47.4,6.89 46.96,7.33 25.53,7.33 25.09,6.89 24.13,6.89 23.86,7.16 23.86,7.67 24.83,8.64 29.86,8.64 30.27,9.05
+V1.8 on Mid 2 "+V1.8_L04_P377" (solid, pour order 377): 56.31,9.6 58.31,11.6 61.42,11.6 61.62,11.8 62.78,11.8 63.48,11.1 63.48,6.95 61.42,6.95 61.42,7.52 61.02,7.92 57.26,7.92 56.86,7.52 56.86,6.95 53.59,6.95 53.59,9.6
+V2.5_ETH on Mid 2 "+V2.5_ETH_L04_P375" (solid, pour order 375): 57.32,7.82 60.96,7.82 61.31,7.47 61.31,6.79 60.94,6.42 57.29,6.42 56.97,6.74 56.97,7.47
+V3.3 on Mid 3 "+V3.3_L05_P380" (solid, pour order 380): 11.31,16.36 11.33,16.36 12.65,17.68 12.65,18.56 8.39,22.82 7.74,22.82 7.56,22.64 7.56,19.81 10.32,17.05 10.32,10.63 9,9.31 9,8.92 9.16,8.76 9.46,8.76 11.08,10.38 11.08,11.3 11.34,11.56 14.25,11.56 14.89,10.92 18.31,10.92 18.47,11.08 18.47,11.48 18.29,11.66 15.17,11.66 14.38,12.45 11.49,12.45 11.31,12.63
+V_SODIMM on Mid 3 "+V_SODIMM_L05_P379" (solid, pour order 379): 62.63,8.74 61.57,7.68 61.57,5 63.5,3.07 67.16,3.07 67.6,3.51 67.6,5.18 65.89,6.89 65.89,7.79 68.1,10 68.1,17.12 68.1,17.55 67.29,18.36 67.29,21.63 68.05,22.39 68.05,24.18 67.52,24.71 61.97,24.71 61.03,23.77 61.03,17.99 62.63,16.39 62.63,15.3 63.54,14.39 63.54,14.1 62.63,13.19 62.63,12.93
+V1.0_ETH on Mid 3 "+V1.0_ETH_L05_P378" (solid, pour order 378): 58.506,15.68 58.506,15.756 58.72,15.97 60.6,15.97 61.71,14.86 62.92,14.86 63.42,14.36 63.42,14.14 62.51,13.23 62.51,8.78 60.49,6.76 58.46,6.76 57.26,7.96 57.26,10.44 57.04,10.66 56.61,10.66 56.17,11.1 56.17,11.37 56.5,11.7 56.88,11.7 58.506,13.326 58.506,13.58
GND on Mid 4 "GND_L07_P389" (solid, pour order 389): 33.63,26.88 35.25,25.26 35.81,25.26 36.82,26.27 36.82,32.71 36.82,33.03 36.59,33.26 35.4,33.26 34.96,32.82 34.48,32.82 33.63,31.97
+V1.8 on Mid 4 "+V1.8_L07_P385" (solid, pour order 385): 62.34,11.13 62,10.79 61.3,10.79 60.88,11.21 60.88,14.27 60.56,14.59 60.56,18 61.14,18.58 61.85,18.58 62.34,18.09 62.34,18.08
GND on GND 2 (split plane): 225 vertices, not listed, extent 0.301,0.301 69.299,34.698
GND on GND 1 (split plane): 225 vertices, not listed, extent 0.301,0.301 69.299,34.698

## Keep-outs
Top Layer:
  circle w0.01: c2.2,31 r2.5
  circle w0.01: c67.4,31 r2.5
  region: 67.6,28.9 67.6,22.005 66.6,22.005 66.6,4.005 69.6,4.005 69.6,28.9
  region: 2,28.9 2,22.005 3,22.005 3,4.005 0,4.005 0,28.9
Bottom Layer:
  circle w0.01: c2.2,31 r2.5
  circle w0.01: c67.4,31 r2.5
  region: 2,28.9 2,22.005 3,22.005 3,4.005 0,4.005 0,28.9
  region: 67.6,28.9 67.6,22.005 66.6,22.005 66.6,4.005 69.6,4.005 69.6,28.9
  region: 0,9.1 4,9.1 4,8 0,8
  region: 2.2,28.9 1.1,28.9 1.1,25 2.2,25
  region: 67.4,28.9 68.5,28.9 68.5,25 67.4,25
  region: 69.6,9.1 65.6,9.1 65.6,8 69.6,8

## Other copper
Top Layer:
  text "PCIe" at 53.9,30.919 h1
  text "USB-SS" at 61.5,30.919 h1
  text "Verdin Lino Adapter / V1.1" at 2.778,8.72 h1 r90
GND 1 (plane layer: these items are gaps in the copper):
  lines w0.4: 66.25,6 66.25,6.48
  lines w0.556: 7,3.75 7.5,3.75 ; 8.5,3.75 9,3.75 ; 10,3.75 10.5,3.75 ; 11.5,3.75 12,3.75 ; 13,3.75 13.5,3.75 ; 19,17 19,17.5 ; 19,20 19,20.5 ; 19,21.25 19,21.75 ; 19.75,18.5 19.75,19 ; 25.75,24.25 25.75,24.75 ; 26.5,19.75 26.5,20.25 ; 26.5,22.75 26.5,23.25 ; 27.25,21.25 27.25,21.75 ; 28.75,20.5 28.75,21 ; 29,4.5 29.5,4.5 ; 29.5,10.75 29.5,11.25 ; 29.5,19 29.5,19.5 ; 30.5,4.5 31,4.5 ; 31,9.25 31,9.75 ; 31,17.5 31,18 ; 32,4.5 32.5,4.5 ; 32.5,8.5 32.5,9 ; 32.5,16.75 32.5,17.25 ; 34,15.25 34,15.75 ; 34.75,34.45 34.75,34.95 ; 35.5,14.5 35.5,15 ; 37,13 37,13.5 ; 38.85,3.75 39.35,3.75 ; 39.25,34.45 39.25,34.95 ; 42.25,13 42.25,13.5 ; 43,11.5 43,12 ; 43.75,22 43.75,22.5 ; 44,3 44.5,3 ; 48.5,3.75 49,3.75 ; 49.75,9.75 49.75,10.25 ; 49.75,12 49.75,12.5 ; 49.75,14.25 49.75,14.75 ; 49.75,17.5 49.75,18 ; 49.75,19.5 49.75,20 ; 50.5,13.75 50.5,14.25 ; 50.5,15.75 50.5,16.25 ; 50.5,18 50.5,18.5 ; 51.25,17 51.25,17.5 ; 52,5.25 52.5,5.25 ; 54.25,5.25 54.75,5.25 ; 56,21.75 56.5,21.75 ; 56.5,19.5 56.5,20 ; 56.75,27 57.25,27 ; 57.6,22 58.1,22 ; 58.25,21 58.75,21 ; 58.75,18.75 58.75,19.25 ; 59,27 59.5,27 ; 65.9,5.65 65.95,5.65 ; 66.25,6.5 66.25,6 66.25,5.35 ; 66.25,5.35 66.25,5.35
GND 2 (plane layer: these items are gaps in the copper):
  lines w0.2: -0.01,34.91 8.5,34.91
  lines w0.4: 66.25,6.48 66.25,6 66.25,6.5
  lines w0.556: 7,3.75 7.5,3.75 ; 8.5,3.75 9,3.75 ; 10,3.75 10.5,3.75 ; 11.5,3.75 12,3.75 ; 13,3.75 13.5,3.75 ; 19,17 19,17.5 ; 19,20 19,20.5 ; 19,21.25 19,21.75 ; 19.75,18.5 19.75,19 ; 25.75,24.25 25.75,24.75 ; 26.5,19.75 26.5,20.25 ; 26.5,22.75 26.5,23.25 ; 27.25,21.25 27.25,21.75 ; 28.75,20.5 28.75,21 ; 29,4.5 29.5,4.5 ; 29.5,10.75 29.5,11.25 ; 29.5,19 29.5,19.5 ; 30.5,4.5 31,4.5 ; 31,9.25 31,9.75 ; 31,17.5 31,18 ; 32,4.5 32.5,4.5 ; 32.5,8.5 32.5,9 ; 32.5,16.75 32.5,17.25 ; 34,15.25 34,15.75 ; 34.75,34.45 34.75,34.95 ; 35.5,14.5 35.5,15 ; 37,13 37,13.5 ; 38.85,3.75 39.35,3.75 ; 39.25,34.45 39.25,34.95 ; 42.25,13 42.25,13.5 ; 43,11.5 43,12 ; 43.75,22 43.75,22.5 ; 44,3 44.5,3 ; 48.5,3.75 49,3.75 ; 49.75,9.75 49.75,10.25 ; 49.75,12 49.75,12.5 ; 49.75,14.25 49.75,14.75 ; 49.75,17.5 49.75,18 ; 49.75,19.5 49.75,20 ; 50.5,13.75 50.5,14.25 ; 50.5,15.75 50.5,16.25 ; 50.5,18 50.5,18.5 ; 51.25,17 51.25,17.5 ; 52,5.25 52.5,5.25 ; 54.25,5.25 54.75,5.25 ; 56,21.75 56.5,21.75 ; 56.5,19.5 56.5,20 ; 56.75,27 57.25,27 ; 57.6,22 58.1,22 ; 58.25,21 58.75,21 ; 58.75,18.75 58.75,19.25 ; 59,27 59.5,27 ; 65.9,5.65 65.95,5.65 ; 66.25,6.5 66.25,6 66.25,5.35 ; 66.25,5.35 66.25,5.35

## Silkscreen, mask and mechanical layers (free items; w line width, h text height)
Top Solder:
  text "ATTENTION" at 32.285,20.947 h0.75
  text "e" at 32.404,20.846 h5
  text "R" at 28.74,20.68 h7
  text "W" at 37.96,20.59 h5
  text "ELECTROSTATIC" at 31.406,20.287 h0.75
  text "SENSITIVE DEVICE" at 31.113,19.652 h0.75
  text "C" at 36.2,16.01 h5
Mechanical 1:
  lines w0.01: 0.005,22 0.005,35 ; 2,22 3,22 3,4 ; 66.6,4 66.6,22 67.6,22 ; 69.595,22 69.595,35
Mechanical 6:
  lines w0.254: 22.8,9 46.8,9 46.8,33 22.8,33 22.8,9
Top Assembly:
  text "Lino Verdin Adapter V1.0 Top Side" at 0.6,35.67 h2
Bottom Assembly:
  text "Lino Verdin Adapter V1.0 Bottom Side" at 69,35.72 h2
Mechanical 15:
  lines w0.1: 0,0 0,6.3 cw(c0.2,6.3) 0.2,6.5 3.5,6.5 ccw(c3.5,7) 4,7 4,7.5 ccw(c3.5,7.5) 3.5,8 0.2,8 cw(c0.2,8.2) 0,8.2 0,18 1.35,18 ccw(c1.35,18.65) 2,18.65 2,21.35 ccw(c1.35,21.35) 1.35,22 0.2,22 cw(c0.2,22.2) 0,22.2 0,35 69.6,35 69.6,22.2 cw(c69.4,22.2) 69.4,22 68.25,22 ccw(c68.25,21.35) 67.6,21.35 67.6,18.65 ccw(c68.25,18.65) 68.25,18 69.6,18 69.6,8.2 cw(c69.4,8.2) 69.4,8 66.1,8 ccw(c66.1,7.5) 65.6,7.5 65.6,7 ccw(c66.1,7) 66.1,6.5 69.4,6.5 cw(c69.4,6.3) 69.6,6.3 69.6,0 38.8,0 38.8,3.5 ccw(c38.3,3.5) 37.8,3.5 37.8,0 0,0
